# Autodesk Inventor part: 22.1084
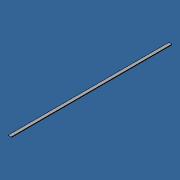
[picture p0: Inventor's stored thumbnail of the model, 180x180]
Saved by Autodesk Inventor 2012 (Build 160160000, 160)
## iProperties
Created: 2007-05
Part Number: 22.1084
Material: PVC-U
Document SubType Name: Modeling
Designer: Andy Moles
Density: 1.4 g/cm^3
Description: CONDUIT 45 TOP
Stock Number: 22.1084 CONDUIT 45 TOP
Author: Andy Moles
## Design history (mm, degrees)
sketch "Sketch1"
  geometry: L1 (20.5, 38.3)-(20.5, 33.5); L2 (-18.8, 40)-(18.8, 40); L3 (-20.5, 33.5)-(-20.5, 38.3); L4 (-19.3, 38.3)-(-19.3, 35.49); L5 (18.8, 38.8)-(-18.8, 38.8); L6 (19.3, 35.49)-(19.3, 38.3); L7 (0, 40)-(0, 40); A1 r 1.5 centre (19, 33.5) between (18.85, 34.992) and (20.5, 33.5); A2 r 1.7 centre (18.8, 38.3) between (20.5, 38.3) and (18.8, 40); A3 r 1.7 centre (-18.8, 38.3) between (-18.8, 40) and (-20.5, 38.3); A4 r 1.5 centre (-19, 33.5) between (-20.5, 33.5) and (-18.85, 34.992); A5 r 0.5 centre (-18.8, 35.49) between (-19.3, 35.49) and (-18.85, 34.992); A6 r 0.5 centre (-18.8, 38.3) between (-18.8, 38.8) and (-19.3, 38.3); A7 r 0.5 centre (18.8, 38.3) between (19.3, 38.3) and (18.8, 38.8); A8 r 0.5 centre (18.8, 35.49) between (18.85, 34.992) and (19.3, 35.49); 1 further point
  constraints: 16 point on circle, 14 end point, 8 centre point, 6 tangent, 4 vertical alignment, 3 horizontal alignment, 1 midpoint, 1 parallel
  dimensions: "d3" = 1.69999 radius of A3; "d4" = 0.5 radius of A6; "d5" = 0.5 radius of A5; "d6" = 1.5 radius of A4; "d7" = 4.80001 distance of L3.start L3.end; "d8" = 2.81003 distance of L4.start L4.end; "d9" = 0.2 horizontal distance of A4.centre A5.centre; "d10" = 1.98997 vertical distance of A5.centre A4.centre; "d11" = 1.2 distance between parallel lines of L4 L3; "d12" = 1.69999 radius of A2; "d13" = 0.5 radius of A7; "d14" = 1.5 radius of A1; "d15" = 0.5 radius of A8; "d16" = 4.80001 distance of L1.start L1.end; "d17" = 2.81003 distance of L6.start L6.end; "d18" = 4.80001 vertical distance of A1.centre A2.centre; "d19" = 0.2 horizontal distance of A1.centre A8.centre; "d20" = 0.15 horizontal distance of A1.centre A1.start; "d21" = 41 distance between parallel lines of L1 L3; "d24" = 20.5 distance from line of L7.end L1 (= 0.5 x d21)
extrude "Extrusion2" new body sketch "Sketch1" stored distance "d27" = 2000; taper "d28" = 0 deg
body "Solid1"
